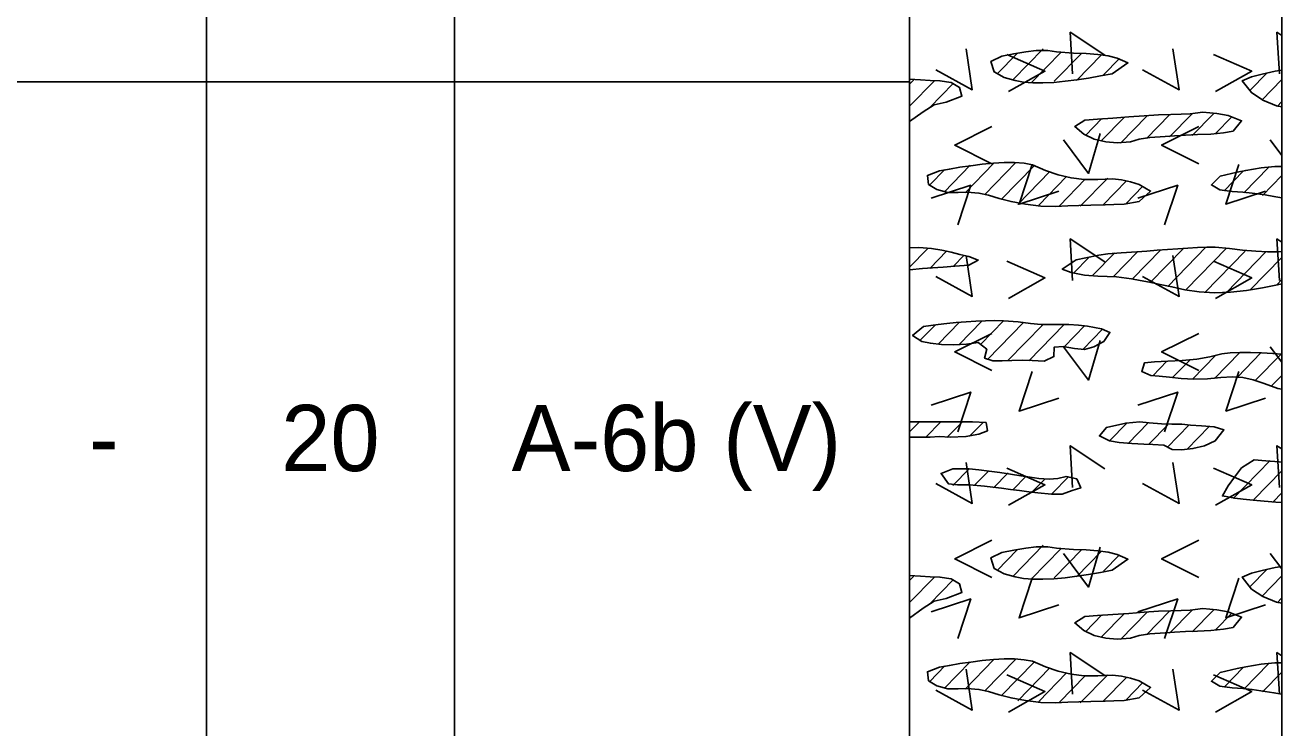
# Model space of a CAD drawing. Extents: x -0.01 to 0.83, y -0.63 to 1.27.
# Drawn here: x 0.7067 to 0.8333, y 0.8677 to 0.9385 of the extents above; entities that cross this region are included whole.
import ezdxf

# ---------------------------------------------------------------- set-up
doc = ezdxf.new("R2010")
doc.units = 0

msp = doc.modelspace()

# ---------------------------------------------------------------- linework, layer by layer
for points in [[(0, 0), (0.83333, 0), (0.83333, 1.275), (0, 1.275)], [(0, 0), (0.83333, 0), (0.83333, 1.275), (0, 1.275)], [(0, 0), (0.83333, 0), (0.83333, 1.275), (0, 1.275)], [(0, 0), (0.83333, 0), (0.83333, 1.275), (0, 1.275)], [(0, 0), (0.83333, 0), (0.83333, 1.275), (0, 1.275)], [(0.81233, 0.93565), (0.81063, 0.93577), (0.80977, 0.93591), (0.8086, 0.93591), (0.80755, 0.93577), (0.80632, 0.93557), (0.80513, 0.93533), (0.80403, 0.93481), (0.80436, 0.93374), (0.80536, 0.93318), (0.80647, 0.93288), (0.8073, 0.93273), (0.80824, 0.93265), (0.80926, 0.93264), (0.81035, 0.93269), (0.81149, 0.9328), (0.81267, 0.93294), (0.81386, 0.93313), (0.81506, 0.93334), (0.81625, 0.93357), (0.81783, 0.93466), (0.81673, 0.93515), (0.81585, 0.93536), (0.8148, 0.93551), (0.81361, 0.93562)], [(0.79583, 0.92874), (0.79719, 0.92973), (0.79831, 0.93044), (0.79951, 0.93071), (0.80111, 0.93131), (0.80086, 0.93219), (0.80002, 0.93267), (0.79889, 0.93286), (0.79791, 0.93289), (0.79694, 0.93295), (0.79583, 0.93303)], [(0.83265, 0.93384), (0.83136, 0.93353), (0.83028, 0.93326), (0.82934, 0.93286), (0.83026, 0.93166), (0.83142, 0.9309), (0.83279, 0.93032), (0.83333, 0.93022), (0.83333, 0.93393)], [(0.82537, 0.92969), (0.82408, 0.92954), (0.82319, 0.92948), (0.82214, 0.92946), (0.82091, 0.92942), (0.81947, 0.92933), (0.81792, 0.92921), (0.81632, 0.92909), (0.81475, 0.92899), (0.81348, 0.92889), (0.81247, 0.92825), (0.81337, 0.92749), (0.81444, 0.92699), (0.81561, 0.9267), (0.81675, 0.9266), (0.81807, 0.92671), (0.81896, 0.92698), (0.82003, 0.92713), (0.82157, 0.92725), (0.82253, 0.92731), (0.82362, 0.92737), (0.82483, 0.92743), (0.82618, 0.92749), (0.82745, 0.9276), (0.82842, 0.92778), (0.82927, 0.92883), (0.82791, 0.92935), (0.82679, 0.92955)], [(0.79885, 0.92378), (0.79763, 0.92332), (0.79773, 0.92242), (0.79859, 0.9219), (0.7997, 0.9216), (0.80074, 0.92161), (0.80165, 0.92163), (0.80281, 0.92154), (0.80377, 0.92134), (0.80486, 0.92099), (0.80606, 0.92069), (0.80751, 0.92042), (0.80905, 0.92023), (0.81052, 0.9202), (0.81177, 0.92026), (0.81289, 0.9203), (0.81408, 0.92033), (0.81553, 0.92037), (0.81642, 0.9204), (0.81745, 0.92043), (0.81897, 0.9207), (0.82011, 0.92174), (0.81896, 0.92241), (0.8181, 0.92268), (0.81717, 0.92287), (0.81626, 0.92298), (0.81479, 0.92292), (0.81343, 0.92292), (0.8121, 0.92307), (0.8108, 0.92337), (0.80953, 0.92383), (0.8082, 0.92438), (0.80736, 0.92454), (0.8064, 0.92462), (0.80536, 0.92462), (0.80427, 0.92456), (0.80314, 0.92445), (0.80201, 0.9243), (0.8009, 0.92414), (0.79984, 0.92396)], [(0.83263, 0.92422), (0.83126, 0.92409), (0.82969, 0.92382), (0.82883, 0.92365), (0.82712, 0.92324), (0.82623, 0.92237), (0.82708, 0.92188), (0.82831, 0.92169), (0.82941, 0.92163), (0.83033, 0.92154), (0.83165, 0.92135), (0.83253, 0.92121), (0.83333, 0.92107), (0.83333, 0.92422)], [(0.79583, 0.91382), (0.79715, 0.91393), (0.79814, 0.91401), (0.79922, 0.91408), (0.80039, 0.91417), (0.80179, 0.91429), (0.80275, 0.9148), (0.80179, 0.91515), (0.80091, 0.91536), (0.80003, 0.91558), (0.79909, 0.91579), (0.79803, 0.91595), (0.79677, 0.91605), (0.79583, 0.91603)], [(0.82816, 0.91157), (0.82978, 0.91174), (0.83137, 0.912), (0.8329, 0.91231), (0.83333, 0.91241), (0.83333, 0.91565), (0.83295, 0.91562), (0.83188, 0.91564), (0.83071, 0.91569), (0.82938, 0.9158), (0.82807, 0.91596), (0.82662, 0.91608), (0.82576, 0.91609), (0.82484, 0.91606), (0.82387, 0.91601), (0.82286, 0.91594), (0.82182, 0.91586), (0.82077, 0.91578), (0.81973, 0.91569), (0.81872, 0.91562), (0.81715, 0.91552), (0.81579, 0.91543), (0.81491, 0.9153), (0.81357, 0.91502), (0.8126, 0.91481), (0.81121, 0.91389), (0.8121, 0.91353), (0.81345, 0.91328), (0.81479, 0.91319), (0.81668, 0.91309), (0.81818, 0.91289), (0.81905, 0.91274), (0.82, 0.91257), (0.82107, 0.91235), (0.82225, 0.9121), (0.82357, 0.91181), (0.82501, 0.91158), (0.82656, 0.91151)], [(0.79708, 0.90659), (0.79794, 0.90641), (0.79904, 0.9063), (0.80028, 0.90627), (0.80156, 0.90632), (0.80274, 0.90648), (0.80361, 0.90582), (0.80338, 0.90492), (0.80422, 0.90465), (0.80517, 0.90463), (0.80613, 0.90469), (0.8072, 0.90472), (0.80818, 0.90469), (0.80939, 0.90461), (0.81037, 0.90508), (0.81038, 0.90602), (0.8113, 0.90609), (0.81244, 0.9059), (0.81346, 0.90579), (0.81438, 0.90605), (0.81539, 0.90659), (0.81601, 0.9075), (0.81517, 0.90788), (0.81374, 0.90815), (0.81285, 0.90825), (0.81187, 0.9083), (0.81, 0.90831), (0.8091, 0.90832), (0.808, 0.9084), (0.80678, 0.90856), (0.8053, 0.90869), (0.80443, 0.9087), (0.80349, 0.90868), (0.80251, 0.90864), (0.80152, 0.90858), (0.80054, 0.9085), (0.79959, 0.90841), (0.7987, 0.90831), (0.79722, 0.90809), (0.79614, 0.90721)], [(0.83241, 0.90537), (0.83129, 0.90544), (0.83017, 0.90547), (0.8291, 0.90548), (0.82811, 0.90544), (0.82728, 0.90535), (0.82608, 0.90505), (0.82476, 0.90482), (0.8233, 0.90469), (0.82183, 0.90461), (0.82051, 0.90455), (0.81951, 0.90445), (0.81922, 0.90358), (0.82013, 0.90316), (0.82097, 0.90311), (0.822, 0.90301), (0.82318, 0.90288), (0.82448, 0.90279), (0.82584, 0.90282), (0.82719, 0.90298), (0.82836, 0.90305), (0.8294, 0.90297), (0.83043, 0.90274), (0.83156, 0.90235), (0.83291, 0.90186), (0.83333, 0.90178), (0.83333, 0.9053)], [(0.79583, 0.89696), (0.79676, 0.89695), (0.79792, 0.89697), (0.79882, 0.89701), (0.79992, 0.89697), (0.80151, 0.89701), (0.80282, 0.89727), (0.80367, 0.89759), (0.80354, 0.89842), (0.80216, 0.89851), (0.79583, 0.89851)], [(0.81822, 0.89632), (0.81944, 0.89626), (0.82033, 0.89622), (0.82145, 0.89615), (0.82229, 0.89573), (0.82324, 0.89569), (0.82438, 0.8958), (0.82555, 0.89608), (0.82662, 0.89659), (0.82749, 0.89769), (0.82651, 0.89799), (0.82524, 0.89809), (0.82413, 0.89815), (0.82324, 0.89826), (0.82226, 0.89828), (0.82121, 0.8983), (0.81995, 0.89839), (0.81902, 0.89851), (0.81761, 0.89837), (0.81566, 0.89793), (0.81496, 0.89709), (0.81598, 0.8966), (0.81695, 0.89642)], [(0.80066, 0.89216), (0.80188, 0.89215), (0.80339, 0.89202), (0.80423, 0.89193), (0.8051, 0.89182), (0.806, 0.8917), (0.80692, 0.89158), (0.80784, 0.89146), (0.80875, 0.89135), (0.81014, 0.89121), (0.81119, 0.89122), (0.81222, 0.89157), (0.81308, 0.89185), (0.81267, 0.89275), (0.8116, 0.893), (0.81075, 0.8928), (0.80989, 0.89272), (0.80885, 0.8928), (0.80799, 0.89291), (0.80703, 0.89305), (0.806, 0.89322), (0.80492, 0.89339), (0.80384, 0.89354), (0.8028, 0.89367), (0.80182, 0.89377), (0.8002, 0.89378), (0.79901, 0.8933), (0.79974, 0.89226)], [(0.83305, 0.89446), (0.83171, 0.89457), (0.83054, 0.89467), (0.82925, 0.89385), (0.82857, 0.89294), (0.82792, 0.89205), (0.82735, 0.89103), (0.82858, 0.8908), (0.82945, 0.8907), (0.83045, 0.8906), (0.83155, 0.89051), (0.83272, 0.89041), (0.83333, 0.89036), (0.83333, 0.89445)], [(0.81233, 0.88565), (0.81063, 0.88577), (0.80977, 0.88591), (0.8086, 0.88591), (0.80755, 0.88577), (0.80632, 0.88557), (0.80513, 0.88533), (0.80403, 0.88481), (0.80436, 0.88374), (0.80536, 0.88318), (0.80647, 0.88288), (0.8073, 0.88273), (0.80824, 0.88265), (0.80926, 0.88264), (0.81035, 0.88269), (0.81149, 0.8828), (0.81267, 0.88294), (0.81386, 0.88313), (0.81506, 0.88334), (0.81625, 0.88357), (0.81783, 0.88466), (0.81673, 0.88515), (0.81585, 0.88536), (0.8148, 0.88551), (0.81361, 0.88562)], [(0.83265, 0.88384), (0.83136, 0.88353), (0.83028, 0.88326), (0.82934, 0.88286), (0.83026, 0.88166), (0.83142, 0.8809), (0.83279, 0.88032), (0.83333, 0.88022), (0.83333, 0.88393)], [(0.79583, 0.87874), (0.79719, 0.87973), (0.79831, 0.88044), (0.79951, 0.88071), (0.80111, 0.88131), (0.80086, 0.88219), (0.80002, 0.88267), (0.79889, 0.88286), (0.79791, 0.88289), (0.79694, 0.88295), (0.79583, 0.88303)], [(0.82537, 0.87969), (0.82408, 0.87954), (0.82319, 0.87948), (0.82214, 0.87946), (0.82091, 0.87942), (0.81947, 0.87933), (0.81792, 0.87921), (0.81632, 0.87909), (0.81475, 0.87899), (0.81348, 0.87889), (0.81247, 0.87825), (0.81337, 0.87749), (0.81444, 0.87699), (0.81561, 0.8767), (0.81675, 0.8766), (0.81807, 0.87671), (0.81896, 0.87698), (0.82003, 0.87713), (0.82157, 0.87725), (0.82253, 0.87731), (0.82362, 0.87737), (0.82483, 0.87743), (0.82618, 0.87749), (0.82745, 0.8776), (0.82842, 0.87778), (0.82927, 0.87883), (0.82791, 0.87935), (0.82679, 0.87955)], [(0.79885, 0.87378), (0.79763, 0.87332), (0.79773, 0.87242), (0.79859, 0.8719), (0.7997, 0.8716), (0.80074, 0.87161), (0.80165, 0.87163), (0.80281, 0.87154), (0.80377, 0.87134), (0.80486, 0.87099), (0.80606, 0.87069), (0.80751, 0.87042), (0.80905, 0.87023), (0.81052, 0.8702), (0.81177, 0.87026), (0.81289, 0.8703), (0.81408, 0.87033), (0.81553, 0.87037), (0.81642, 0.8704), (0.81745, 0.87043), (0.81897, 0.8707), (0.82011, 0.87174), (0.81896, 0.87241), (0.8181, 0.87268), (0.81717, 0.87287), (0.81626, 0.87298), (0.81479, 0.87292), (0.81343, 0.87292), (0.8121, 0.87307), (0.8108, 0.87337), (0.80953, 0.87383), (0.8082, 0.87438), (0.80736, 0.87454), (0.8064, 0.87462), (0.80536, 0.87462), (0.80427, 0.87456), (0.80314, 0.87445), (0.80201, 0.8743), (0.8009, 0.87414), (0.79984, 0.87396)], [(0.83263, 0.87423), (0.83126, 0.87409), (0.82969, 0.87382), (0.82883, 0.87365), (0.82712, 0.87324), (0.82623, 0.87237), (0.82708, 0.87188), (0.82831, 0.87169), (0.82941, 0.87163), (0.83033, 0.87154), (0.83165, 0.87135), (0.83253, 0.87121), (0.83333, 0.87107), (0.83333, 0.87422)]]:
    msp.add_lwpolyline(points, close=True)
for points in [[(0.725, 1.22083), (0.725, -0.62183)], [(0.75, 1.22083), (0.75, -0.62183)], [(0.75, 1.22083), (0.75, -0.62183)], [(0.79583, 1.22083), (0.79583, -0.62183)], [(0.725, 1.20833), (0.725, -0.62183)], [(0.83333, -0.62183), (0.83333, 1.13843)], [(0.81551, 0.93544), (0.81201, 0.93775), (0.81226, 0.93357)], [(0.83333, 0.93743), (0.83284, 0.93775), (0.83309, 0.93357)], [(0.79847, 0.93396), (0.80215, 0.93196), (0.80153, 0.93608)], [(0.80465, 0.93354), (0.80667, 0.93561)], [(0.80562, 0.9355), (0.80946, 0.93382), (0.80581, 0.93176)], [(0.80626, 0.93297), (0.80928, 0.93607)], [(0.80809, 0.93264), (0.81111, 0.93573)], [(0.81041, 0.9328), (0.81318, 0.93563)], [(0.81264, 0.93288), (0.81518, 0.93548)], [(0.8193, 0.93396), (0.82299, 0.93196), (0.82236, 0.93608)], [(0.82645, 0.9355), (0.83029, 0.93382), (0.82664, 0.93176)], [(0.81536, 0.93345), (0.81699, 0.93511)], [(0.7963, 0.93299), (0.79583, 0.93251)], [(0.8301, 0.93187), (0.83184, 0.93366)], [(0.83131, 0.9309), (0.83333, 0.93298)], [(0.70417, 0.93275), (0.725, 0.93275)], [(0.725, 0.93275), (0.75, 0.93275)], [(0.75, 0.93275), (0.79583, 0.93275)], [(0.79834, 0.93286), (0.79583, 0.93029)], [(0.79786, 0.93016), (0.80023, 0.93259)], [(0.83285, 0.93027), (0.83333, 0.93076)], [(0.81514, 0.9268), (0.81748, 0.92919)], [(0.81709, 0.92658), (0.81974, 0.9293)], [(0.8197, 0.92703), (0.82203, 0.92943)], [(0.82202, 0.9272), (0.8243, 0.92954)], [(0.82431, 0.92733), (0.82644, 0.92952)], [(0.82663, 0.9275), (0.82834, 0.92925)], [(0.80412, 0.92825), (0.80038, 0.92637), (0.80412, 0.9245)], [(0.81519, 0.92906), (0.81354, 0.92736)], [(0.82496, 0.92825), (0.82121, 0.92637), (0.82496, 0.9245)], [(0.81134, 0.92691), (0.81384, 0.92353), (0.81503, 0.92753)], [(0.83217, 0.92691), (0.83333, 0.92534)], [(0.79933, 0.92165), (0.80195, 0.92434)], [(0.80142, 0.92158), (0.8043, 0.92453)], [(0.80653, 0.92461), (0.8034, 0.92139)], [(0.80506, 0.92089), (0.8084, 0.92431)], [(0.80818, 0.92441), (0.80687, 0.92041), (0.81087, 0.92173)], [(0.82901, 0.92441), (0.8277, 0.92041), (0.8317, 0.92173)], [(0.83203, 0.92417), (0.82949, 0.92157)], [(0.79938, 0.92391), (0.79786, 0.92236)], [(0.80997, 0.92371), (0.80675, 0.9204)], [(0.81164, 0.9232), (0.80884, 0.92034)], [(0.81353, 0.92293), (0.81094, 0.92027)], [(0.81303, 0.92021), (0.81579, 0.92303)], [(0.82751, 0.92176), (0.82945, 0.92375)], [(0.83138, 0.9213), (0.83333, 0.9233)], [(0.80069, 0.91833), (0.802, 0.92233), (0.798, 0.92102)], [(0.81534, 0.92036), (0.81768, 0.92276)], [(0.8176, 0.92047), (0.81934, 0.92225)], [(0.82152, 0.91833), (0.82284, 0.92233), (0.81884, 0.92102)], [(0.83333, 0.92108), (0.83333, 0.92109)], [(0.81551, 0.91461), (0.81201, 0.91692), (0.81226, 0.91273)], [(0.83333, 0.9166), (0.83284, 0.91692), (0.83309, 0.91273)], [(0.79765, 0.91594), (0.79583, 0.91407)], [(0.7996, 0.91572), (0.79786, 0.91394)], [(0.79847, 0.91313), (0.80215, 0.91113), (0.80153, 0.91525)], [(0.8013, 0.91524), (0.80027, 0.91419)], [(0.8143, 0.91326), (0.8165, 0.91551)], [(0.8164, 0.91319), (0.81879, 0.91564)], [(0.81829, 0.91291), (0.82114, 0.91584)], [(0.8193, 0.91313), (0.82299, 0.91113), (0.82236, 0.91525)], [(0.82004, 0.91249), (0.82346, 0.916)], [(0.82569, 0.91608), (0.82184, 0.91213)], [(0.82775, 0.91598), (0.8237, 0.91183)], [(0.82964, 0.9157), (0.82557, 0.91152)], [(0.83173, 0.91563), (0.82774, 0.91154)], [(0.80562, 0.91467), (0.80946, 0.91299), (0.80581, 0.91093)], [(0.81392, 0.91508), (0.81235, 0.91348)], [(0.82645, 0.91467), (0.83029, 0.91299), (0.82664, 0.91093)], [(0.83333, 0.91506), (0.83012, 0.91176)], [(0.83281, 0.91231), (0.83333, 0.91284)], [(0.79844, 0.90828), (0.79691, 0.90671)], [(0.79871, 0.90634), (0.80085, 0.90853)], [(0.80083, 0.90629), (0.80311, 0.90863)], [(0.80534, 0.90871), (0.80299, 0.90629)], [(0.80367, 0.90478), (0.80732, 0.90852)], [(0.80571, 0.90466), (0.80924, 0.90828)], [(0.81142, 0.90829), (0.80785, 0.90464)], [(0.81141, 0.90607), (0.81348, 0.90819)], [(0.81528, 0.90783), (0.81331, 0.90581)], [(0.80412, 0.90741), (0.80038, 0.90554), (0.80412, 0.90366)], [(0.81134, 0.90607), (0.81384, 0.9027), (0.81503, 0.9067)], [(0.82496, 0.90741), (0.82121, 0.90554), (0.82496, 0.90366)], [(0.82433, 0.9028), (0.82666, 0.90519)], [(0.82909, 0.90548), (0.82656, 0.90288)], [(0.82885, 0.90301), (0.83122, 0.90544)], [(0.83325, 0.90531), (0.83065, 0.90265)], [(0.83217, 0.90607), (0.83333, 0.90451)], [(0.82035, 0.90315), (0.82176, 0.9046)], [(0.82233, 0.90298), (0.82408, 0.90476)], [(0.80818, 0.90358), (0.80687, 0.89958), (0.81087, 0.90089)], [(0.82901, 0.90358), (0.8277, 0.89958), (0.8317, 0.90089)], [(0.83333, 0.90318), (0.83227, 0.90209)], [(0.80069, 0.8975), (0.802, 0.9015), (0.798, 0.90019)], [(0.82152, 0.8975), (0.82284, 0.9015), (0.81884, 0.90019)], [(0.79583, 0.89748), (0.79681, 0.89848)], [(0.79898, 0.8985), (0.79747, 0.89695)], [(0.80116, 0.89851), (0.79959, 0.89691)], [(0.80328, 0.89847), (0.80188, 0.89704)], [(0.8177, 0.89837), (0.81596, 0.89659)], [(0.81988, 0.89839), (0.81785, 0.89631)], [(0.82185, 0.8982), (0.81997, 0.89627)], [(0.824, 0.89819), (0.82178, 0.89591)], [(0.82601, 0.89803), (0.82378, 0.89575)], [(0.81551, 0.89377), (0.81201, 0.89609), (0.81226, 0.8919)], [(0.83333, 0.89577), (0.83284, 0.89609), (0.83309, 0.8919)], [(0.79847, 0.89229), (0.80215, 0.89029), (0.80153, 0.89442)], [(0.80188, 0.89381), (0.8002, 0.89209)], [(0.80562, 0.89384), (0.80946, 0.89215), (0.80581, 0.89009)], [(0.8193, 0.89229), (0.82299, 0.89029), (0.82236, 0.89442)], [(0.82645, 0.89384), (0.83029, 0.89215), (0.82664, 0.89009)], [(0.83217, 0.89459), (0.82844, 0.89077)], [(0.8038, 0.89357), (0.80237, 0.89211)], [(0.80575, 0.89335), (0.80429, 0.89186)], [(0.80758, 0.89302), (0.80627, 0.89167)], [(0.80941, 0.89269), (0.80816, 0.8914)], [(0.81188, 0.893), (0.81016, 0.89124)], [(0.83333, 0.89357), (0.83052, 0.89069)], [(0.83333, 0.89136), (0.83245, 0.89045)], [(0.80412, 0.88658), (0.80038, 0.8847), (0.80412, 0.88283)], [(0.82496, 0.88658), (0.82121, 0.8847), (0.82496, 0.88283)], [(0.80465, 0.88354), (0.80667, 0.88561)], [(0.80626, 0.88297), (0.80928, 0.88607)], [(0.80809, 0.88264), (0.81111, 0.88573)], [(0.81041, 0.8828), (0.81318, 0.88563)], [(0.81134, 0.88524), (0.81384, 0.88186), (0.81503, 0.88586)], [(0.81264, 0.88288), (0.81518, 0.88548)], [(0.81536, 0.88345), (0.81699, 0.88511)], [(0.83217, 0.88524), (0.83333, 0.88368)], [(0.8301, 0.88187), (0.83184, 0.88366)], [(0.7963, 0.88299), (0.79583, 0.88251)], [(0.79834, 0.88286), (0.79583, 0.88029)], [(0.79786, 0.88016), (0.80023, 0.88259)], [(0.80818, 0.88275), (0.80687, 0.87875), (0.81087, 0.88006)], [(0.82901, 0.88275), (0.8277, 0.87875), (0.8317, 0.88006)], [(0.83131, 0.8809), (0.83333, 0.88298)], [(0.80069, 0.87667), (0.802, 0.88067), (0.798, 0.87936)], [(0.82152, 0.87667), (0.82284, 0.88067), (0.81884, 0.87936)], [(0.83285, 0.88027), (0.83333, 0.88076)], [(0.81519, 0.87906), (0.81354, 0.87736)], [(0.81514, 0.8768), (0.81748, 0.87919)], [(0.81709, 0.87658), (0.81974, 0.8793)], [(0.8197, 0.87703), (0.82203, 0.87943)], [(0.82202, 0.8772), (0.8243, 0.87954)], [(0.82431, 0.87733), (0.82644, 0.87952)], [(0.82663, 0.8775), (0.82834, 0.87925)], [(0.81551, 0.87294), (0.81201, 0.87525), (0.81226, 0.87107)], [(0.83333, 0.87493), (0.83284, 0.87525), (0.83309, 0.87107)], [(0.79938, 0.87391), (0.79786, 0.87236)], [(0.79847, 0.87146), (0.80215, 0.86946), (0.80153, 0.87358)], [(0.79933, 0.87165), (0.80195, 0.87434)], [(0.80142, 0.87158), (0.8043, 0.87453)], [(0.80653, 0.87461), (0.8034, 0.87139)], [(0.80506, 0.87089), (0.8084, 0.87431)], [(0.80997, 0.87371), (0.80675, 0.8704)], [(0.8193, 0.87146), (0.82299, 0.86946), (0.82236, 0.87358)], [(0.82751, 0.87176), (0.82945, 0.87375)], [(0.83203, 0.87417), (0.82949, 0.87157)], [(0.80562, 0.873), (0.80946, 0.87132), (0.80581, 0.86926)], [(0.81164, 0.8732), (0.80884, 0.87034)], [(0.81353, 0.87293), (0.81094, 0.87027)], [(0.81303, 0.87021), (0.81579, 0.87303)], [(0.81534, 0.87036), (0.81768, 0.87276)], [(0.8176, 0.87047), (0.81934, 0.87225)], [(0.82645, 0.873), (0.83029, 0.87132), (0.82664, 0.86926)], [(0.83138, 0.8713), (0.83333, 0.8733)], [(0.83333, 0.87108), (0.83333, 0.87109)]]:
    msp.add_lwpolyline(points)

# ---------------------------------------------------------------- texts
for s, height, p in [('20', 0.006667, (0.73254, 0.89354)), ('A-6b (V)', 0.006667, (0.75575, 0.89354)), ('-', 0.00667, (0.71318, 0.89354))]:
    msp.add_text(s, height=height).set_placement(p)

doc.saveas('drawing.dxf')
